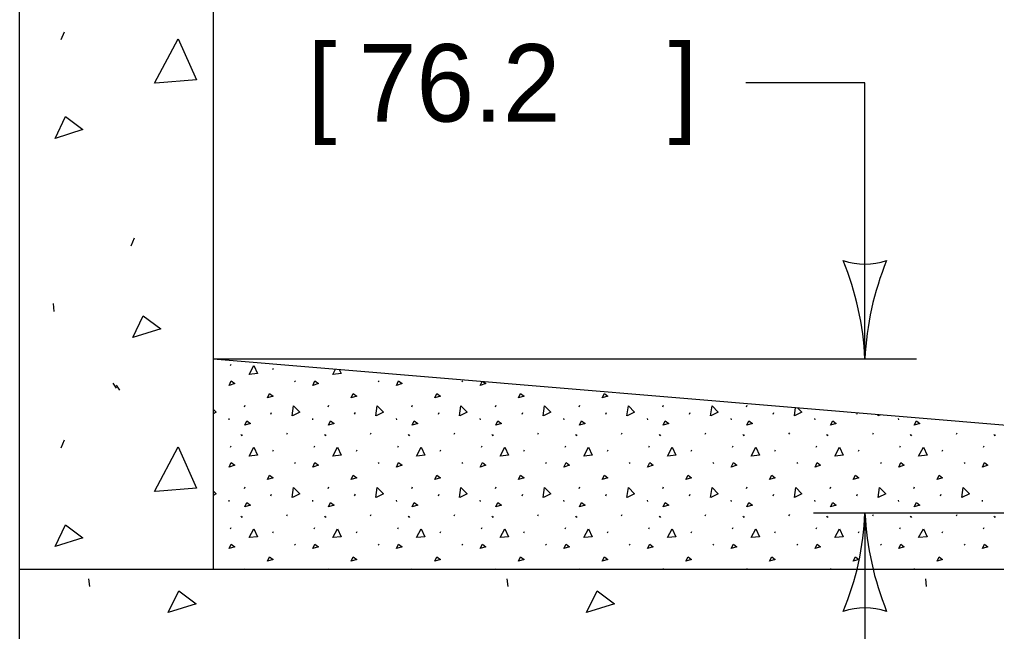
# Model space of a CAD drawing. Extents: x 49991.4 to 50041.6, y 49987.6 to 50011.4.
# Drawn here: x 50025.993 to 50026.75, y 49991.279 to 49991.752 of the extents above; entities that cross this region are included whole.
import ezdxf

# ---------------------------------------------------------------- set-up
doc = ezdxf.new("R2010")
doc.units = 0
for name, color, linetype in [('Level 1', 7, 'Continuous'), ('Level 2', 7, 'Continuous'), ('Level 3', 7, 'Continuous'), ('Level 4', 7, 'Continuous')]:
    doc.layers.add(name, color=color, linetype=linetype)

msp = doc.modelspace()

# ---------------------------------------------------------------- linework, layer by layer
at = {"layer": 'Level 1'}
for p, q in [((50025.99318, 49991.32695), (50025.99318, 49992.22695)), ((50026.0254, 49991.73689), (50026.02811, 49991.74298)), ((50026.07955, 49991.5772), (50026.08225, 49991.58329)), ((50026.01914, 49991.53246), (50026.01982, 49991.52637)), ((50026.14318, 49991.48968), (50027.58032, 49991.36954)), ((50026.06533, 49991.47097), (50026.06804, 49991.46691)), ((50026.06804, 49991.46942), (50026.07074, 49991.46536)), ((50026.0254, 49991.42081), (50026.02811, 49991.4269)), ((50026.04658, 49991.31948), (50026.04726, 49991.31339)), ((50026.37071, 49991.31948), (50026.37139, 49991.31339)), ((50026.69485, 49991.31948), (50026.69553, 49991.31339))]:
    msp.add_line(p, q, dxfattribs=at)
for points in [[(50025.99318, 49992.22695), (50026.14318, 49992.22695), (50026.14318, 49991.32695)], [(50026.09782, 49991.70306), (50026.11609, 49991.73757), (50026.1303, 49991.70577), (50026.09849, 49991.70306)], [(50026.02066, 49991.66043), (50026.02878, 49991.67735), (50026.04232, 49991.6672), (50026.02066, 49991.66043)], [(50026.0809, 49991.50615), (50026.08902, 49991.52307), (50026.10255, 49991.51292), (50026.0809, 49991.50615)], [(50026.09782, 49991.38698), (50026.11609, 49991.42148), (50026.1303, 49991.38968), (50026.09849, 49991.38698)], [(50026.02066, 49991.34434), (50026.02878, 49991.36126), (50026.04232, 49991.35111), (50026.02066, 49991.34434)], [(50025.99318, 49991.14695), (50025.99318, 49991.32695), (50027.72873, 49991.32695), (50027.72873, 49991.14695)], [(50026.10834, 49991.29317), (50026.11646, 49991.31009), (50026.12999, 49991.29994), (50026.10834, 49991.29317)], [(50026.43247, 49991.29317), (50026.44059, 49991.31009), (50026.45413, 49991.29994), (50026.43247, 49991.29317)]]:
    msp.add_lwpolyline(points, dxfattribs=at)
at = {"layer": 'Level 3'}
for p, q in [((50026.64808, 49991.70338), (50026.55581, 49991.70338)), ((50026.64808, 49991.48968), (50026.64808, 49991.70338)), ((50026.14318, 49991.48968), (50026.68808, 49991.48968)), ((50026.64808, 49991.37025), (50026.60808, 49991.37025)), ((50027.57184, 49991.37025), (50026.64808, 49991.37025)), ((50026.64808, 49991.37025), (50026.64808, 49991.09143))]:
    msp.add_line(p, q, dxfattribs=at)
for centre, radius, start, end in [((50026.64808, 49991.61789), 0.05477, 252.13882, 287.86118), ((50026.41536, 49991.47818), 0.233, 2.82731, 22.07716), ((50026.64808, 49991.61789), 0.05477, 252.13882, 287.86118), ((50026.41536, 49991.47818), 0.233, 2.82731, 22.07716), ((50026.87021, 49991.48052), 0.22232, 157.45601, 177.63952), ((50026.87021, 49991.48052), 0.22232, 157.45601, 177.63952), ((50026.42594, 49991.37941), 0.22232, 337.45601, 357.63952), ((50026.88079, 49991.38175), 0.233, 182.82731, 202.07716), ((50026.64808, 49991.24204), 0.05477, 72.13882, 107.86118)]:
    msp.add_arc(centre, radius, start, end, dxfattribs=at)
at = {"layer": 'Level 4'}
for p, q in [((50026.15653, 49991.48446), (50026.15707, 49991.48568)), ((50026.18929, 49991.48135), (50026.18983, 49991.48256)), ((50026.2062, 49991.47268), (50026.20674, 49991.47187)), ((50026.27103, 49991.47268), (50026.27157, 49991.47187)), ((50026.33586, 49991.47268), (50026.3364, 49991.47187)), ((50026.16736, 49991.45252), (50026.1679, 49991.45374)), ((50026.23219, 49991.45252), (50026.23273, 49991.45374)), ((50026.29702, 49991.45252), (50026.29756, 49991.45374)), ((50026.36184, 49991.45252), (50026.36239, 49991.45374)), ((50026.42667, 49991.45252), (50026.42721, 49991.45374)), ((50026.4915, 49991.45252), (50026.49204, 49991.45374)), ((50026.55633, 49991.45252), (50026.55687, 49991.45374)), ((50026.18793, 49991.44697), (50026.18847, 49991.44819)), ((50026.25276, 49991.44697), (50026.2533, 49991.44819)), ((50026.31759, 49991.44697), (50026.31813, 49991.44819)), ((50026.38242, 49991.44697), (50026.38296, 49991.44819)), ((50026.44724, 49991.44697), (50026.44778, 49991.44819)), ((50026.51207, 49991.44697), (50026.51261, 49991.44819)), ((50026.5769, 49991.44697), (50026.57744, 49991.44819)), ((50026.64173, 49991.44697), (50026.64217, 49991.44797)), ((50026.15528, 49991.44357), (50026.15542, 49991.44235)), ((50026.22011, 49991.44357), (50026.22024, 49991.44235)), ((50026.28494, 49991.44357), (50026.28507, 49991.44235)), ((50026.34976, 49991.44357), (50026.3499, 49991.44235)), ((50026.41459, 49991.44357), (50026.41473, 49991.44235)), ((50026.47942, 49991.44357), (50026.47955, 49991.44235)), ((50026.54425, 49991.44357), (50026.54438, 49991.44235)), ((50026.60907, 49991.44357), (50026.60921, 49991.44235)), ((50026.6739, 49991.44357), (50026.67404, 49991.44235)), ((50026.16452, 49991.43127), (50026.16506, 49991.43046)), ((50026.16506, 49991.43096), (50026.1656, 49991.43015)), ((50026.20025, 49991.43127), (50026.20079, 49991.43249)), ((50026.22935, 49991.43127), (50026.22989, 49991.43046)), ((50026.22989, 49991.43096), (50026.23043, 49991.43015)), ((50026.26508, 49991.43127), (50026.26562, 49991.43249)), ((50026.29417, 49991.43127), (50026.29471, 49991.43046)), ((50026.29471, 49991.43096), (50026.29526, 49991.43015)), ((50026.3299, 49991.43127), (50026.33044, 49991.43249)), ((50026.359, 49991.43127), (50026.35954, 49991.43046)), ((50026.35954, 49991.43096), (50026.36008, 49991.43015)), ((50026.39473, 49991.43127), (50026.39527, 49991.43249)), ((50026.42383, 49991.43127), (50026.42437, 49991.43046)), ((50026.42437, 49991.43096), (50026.42491, 49991.43015)), ((50026.45956, 49991.43127), (50026.4601, 49991.43249)), ((50026.48866, 49991.43127), (50026.4892, 49991.43046)), ((50026.4892, 49991.43096), (50026.48974, 49991.43015)), ((50026.52439, 49991.43127), (50026.52493, 49991.43249)), ((50026.55348, 49991.43127), (50026.55402, 49991.43046)), ((50026.55402, 49991.43096), (50026.55457, 49991.43015)), ((50026.58921, 49991.43127), (50026.58975, 49991.43249)), ((50026.61831, 49991.43127), (50026.61885, 49991.43046)), ((50026.61885, 49991.43096), (50026.61939, 49991.43015)), ((50026.65404, 49991.43127), (50026.65458, 49991.43249)), ((50026.68314, 49991.43127), (50026.68368, 49991.43046)), ((50026.68368, 49991.43096), (50026.68422, 49991.43015)), ((50026.71887, 49991.43127), (50026.71941, 49991.43249)), ((50026.74797, 49991.43127), (50026.74851, 49991.43046)), ((50026.74851, 49991.43096), (50026.74905, 49991.43015)), ((50026.15653, 49991.42124), (50026.15707, 49991.42246)), ((50026.22136, 49991.42124), (50026.2219, 49991.42246)), ((50026.28619, 49991.42124), (50026.28673, 49991.42246)), ((50026.35102, 49991.42124), (50026.35156, 49991.42246)), ((50026.41584, 49991.42124), (50026.41638, 49991.42246)), ((50026.48067, 49991.42124), (50026.48121, 49991.42246)), ((50026.5455, 49991.42124), (50026.54604, 49991.42246)), ((50026.61033, 49991.42124), (50026.61087, 49991.42246)), ((50026.67515, 49991.42124), (50026.67569, 49991.42246)), ((50026.73998, 49991.42124), (50026.74052, 49991.42246)), ((50026.18929, 49991.41813), (50026.18983, 49991.41935)), ((50026.25411, 49991.41813), (50026.25465, 49991.41935)), ((50026.31894, 49991.41813), (50026.31948, 49991.41935)), ((50026.38377, 49991.41813), (50026.38431, 49991.41935)), ((50026.4486, 49991.41813), (50026.44914, 49991.41935)), ((50026.51342, 49991.41813), (50026.51396, 49991.41935)), ((50026.57825, 49991.41813), (50026.57879, 49991.41935)), ((50026.64308, 49991.41813), (50026.64362, 49991.41935)), ((50026.70791, 49991.41813), (50026.70845, 49991.41935)), ((50026.2062, 49991.40947), (50026.20674, 49991.40865)), ((50026.27103, 49991.40947), (50026.27157, 49991.40865)), ((50026.33586, 49991.40947), (50026.3364, 49991.40865)), ((50026.40069, 49991.40947), (50026.40123, 49991.40865)), ((50026.46551, 49991.40947), (50026.46605, 49991.40865)), ((50026.53034, 49991.40947), (50026.53088, 49991.40865)), ((50026.59517, 49991.40947), (50026.59571, 49991.40865)), ((50026.66, 49991.40947), (50026.66054, 49991.40865)), ((50026.72482, 49991.40947), (50026.72536, 49991.40865)), ((50026.16736, 49991.3893), (50026.1679, 49991.39052)), ((50026.18793, 49991.38375), (50026.18847, 49991.38497)), ((50026.23219, 49991.3893), (50026.23273, 49991.39052)), ((50026.25276, 49991.38375), (50026.2533, 49991.38497)), ((50026.29702, 49991.3893), (50026.29756, 49991.39052)), ((50026.31759, 49991.38375), (50026.31813, 49991.38497)), ((50026.36184, 49991.3893), (50026.36239, 49991.39052)), ((50026.38242, 49991.38375), (50026.38296, 49991.38497)), ((50026.42667, 49991.3893), (50026.42721, 49991.39052)), ((50026.44724, 49991.38375), (50026.44778, 49991.38497)), ((50026.4915, 49991.3893), (50026.49204, 49991.39052)), ((50026.51207, 49991.38375), (50026.51261, 49991.38497)), ((50026.55633, 49991.3893), (50026.55687, 49991.39052)), ((50026.5769, 49991.38375), (50026.57744, 49991.38497)), ((50026.62115, 49991.3893), (50026.6217, 49991.39052)), ((50026.64173, 49991.38375), (50026.64227, 49991.38497)), ((50026.68598, 49991.3893), (50026.68652, 49991.39052)), ((50026.70655, 49991.38375), (50026.70709, 49991.38497)), ((50026.15528, 49991.38035), (50026.15542, 49991.37914)), ((50026.22011, 49991.38035), (50026.22024, 49991.37914)), ((50026.28494, 49991.38035), (50026.28507, 49991.37914)), ((50026.34976, 49991.38035), (50026.3499, 49991.37914)), ((50026.41459, 49991.38035), (50026.41473, 49991.37914)), ((50026.47942, 49991.38035), (50026.47955, 49991.37914)), ((50026.54425, 49991.38035), (50026.54438, 49991.37914)), ((50026.60907, 49991.38035), (50026.60921, 49991.37914)), ((50026.6739, 49991.38035), (50026.67404, 49991.37914)), ((50026.73873, 49991.38035), (50026.73886, 49991.37914)), ((50026.20025, 49991.36806), (50026.20079, 49991.36927)), ((50026.26508, 49991.36806), (50026.26562, 49991.36927)), ((50026.3299, 49991.36806), (50026.33044, 49991.36927)), ((50026.39473, 49991.36806), (50026.39527, 49991.36927)), ((50026.45956, 49991.36806), (50026.4601, 49991.36927)), ((50026.52439, 49991.36806), (50026.52493, 49991.36927)), ((50026.58921, 49991.36806), (50026.58975, 49991.36927)), ((50026.65404, 49991.36806), (50026.65458, 49991.36927)), ((50026.71887, 49991.36806), (50026.71941, 49991.36927)), ((50026.16452, 49991.36806), (50026.16506, 49991.36724)), ((50026.16506, 49991.36775), (50026.1656, 49991.36693)), ((50026.22935, 49991.36806), (50026.22989, 49991.36724)), ((50026.22989, 49991.36775), (50026.23043, 49991.36693)), ((50026.29417, 49991.36806), (50026.29471, 49991.36724)), ((50026.29471, 49991.36775), (50026.29526, 49991.36693)), ((50026.359, 49991.36806), (50026.35954, 49991.36724)), ((50026.35954, 49991.36775), (50026.36008, 49991.36693)), ((50026.42383, 49991.36806), (50026.42437, 49991.36724)), ((50026.42437, 49991.36775), (50026.42491, 49991.36693)), ((50026.48866, 49991.36806), (50026.4892, 49991.36724)), ((50026.4892, 49991.36775), (50026.48974, 49991.36693)), ((50026.55348, 49991.36806), (50026.55402, 49991.36724)), ((50026.55402, 49991.36775), (50026.55457, 49991.36693)), ((50026.61831, 49991.36806), (50026.61885, 49991.36724)), ((50026.61885, 49991.36775), (50026.61939, 49991.36693)), ((50026.68314, 49991.36806), (50026.68368, 49991.36724)), ((50026.68368, 49991.36775), (50026.68422, 49991.36693)), ((50026.74797, 49991.36806), (50026.74851, 49991.36724)), ((50026.74851, 49991.36775), (50026.74905, 49991.36693)), ((50026.15653, 49991.35802), (50026.15707, 49991.35924)), ((50026.18929, 49991.35491), (50026.18983, 49991.35613)), ((50026.22136, 49991.35802), (50026.2219, 49991.35924)), ((50026.25411, 49991.35491), (50026.25465, 49991.35613)), ((50026.28619, 49991.35802), (50026.28673, 49991.35924)), ((50026.31894, 49991.35491), (50026.31948, 49991.35613)), ((50026.35102, 49991.35802), (50026.35156, 49991.35924)), ((50026.38377, 49991.35491), (50026.38431, 49991.35613)), ((50026.41584, 49991.35802), (50026.41638, 49991.35924)), ((50026.4486, 49991.35491), (50026.44914, 49991.35613)), ((50026.48067, 49991.35802), (50026.48121, 49991.35924)), ((50026.51342, 49991.35491), (50026.51396, 49991.35613)), ((50026.5455, 49991.35802), (50026.54604, 49991.35924)), ((50026.57825, 49991.35491), (50026.57879, 49991.35613)), ((50026.61033, 49991.35802), (50026.61087, 49991.35924)), ((50026.64308, 49991.35491), (50026.64362, 49991.35613)), ((50026.67515, 49991.35802), (50026.67569, 49991.35924)), ((50026.70791, 49991.35491), (50026.70845, 49991.35613)), ((50026.73998, 49991.35802), (50026.74052, 49991.35924)), ((50026.2062, 49991.34625), (50026.20674, 49991.34544)), ((50026.27103, 49991.34625), (50026.27157, 49991.34544)), ((50026.33586, 49991.34625), (50026.3364, 49991.34544)), ((50026.40069, 49991.34625), (50026.40123, 49991.34544)), ((50026.46551, 49991.34625), (50026.46605, 49991.34544)), ((50026.53034, 49991.34625), (50026.53088, 49991.34544)), ((50026.59517, 49991.34625), (50026.59571, 49991.34544)), ((50026.66, 49991.34625), (50026.66054, 49991.34544)), ((50026.72482, 49991.34625), (50026.72536, 49991.34544)), ((50026.16774, 49991.32695), (50026.1679, 49991.3273)), ((50026.23257, 49991.32695), (50026.23273, 49991.3273)), ((50026.2974, 49991.32695), (50026.29756, 49991.3273)), ((50026.36223, 49991.32695), (50026.36239, 49991.3273)), ((50026.42705, 49991.32695), (50026.42721, 49991.3273)), ((50026.49188, 49991.32695), (50026.49204, 49991.3273)), ((50026.55671, 49991.32695), (50026.55687, 49991.3273)), ((50026.62154, 49991.32695), (50026.6217, 49991.3273)), ((50026.68636, 49991.32695), (50026.68652, 49991.3273))]:
    msp.add_line(p, q, dxfattribs=at)
for points in [[(50026.17102, 49991.47769), (50026.17467, 49991.48459), (50026.17751, 49991.47823), (50026.17115, 49991.47769)], [(50026.23584, 49991.47769), (50026.23799, 49991.48175)], [(50026.24088, 49991.48151), (50026.24234, 49991.47823), (50026.23598, 49991.47769)], [(50026.15559, 49991.46917), (50026.15721, 49991.47255), (50026.15992, 49991.47052), (50026.15559, 49991.46917)], [(50026.22041, 49991.46917), (50026.22204, 49991.47255), (50026.22474, 49991.47052), (50026.22041, 49991.46917)], [(50026.28524, 49991.46917), (50026.28686, 49991.47255), (50026.28957, 49991.47052), (50026.28524, 49991.46917)], [(50026.35007, 49991.46917), (50026.35155, 49991.47226)], [(50026.35214, 49991.47221), (50026.3544, 49991.47052), (50026.35007, 49991.46917)], [(50026.18525, 49991.45949), (50026.18688, 49991.46288), (50026.18958, 49991.46085), (50026.18525, 49991.45949)], [(50026.25008, 49991.45949), (50026.2517, 49991.46288), (50026.25441, 49991.46085), (50026.25008, 49991.45949)], [(50026.31491, 49991.45949), (50026.31653, 49991.46288), (50026.31924, 49991.46085), (50026.31491, 49991.45949)], [(50026.37974, 49991.45949), (50026.38136, 49991.46288), (50026.38407, 49991.46085), (50026.37974, 49991.45949)], [(50026.44456, 49991.45949), (50026.44619, 49991.46288), (50026.44889, 49991.46085), (50026.44456, 49991.45949)], [(50026.2044, 49991.44557), (50026.20547, 49991.45331), (50026.21032, 49991.4483), (50026.20452, 49991.44562)], [(50026.26922, 49991.44557), (50026.2703, 49991.45331), (50026.27514, 49991.4483), (50026.26935, 49991.44562)], [(50026.33405, 49991.44557), (50026.33512, 49991.45331), (50026.33997, 49991.4483), (50026.33418, 49991.44562)], [(50026.39888, 49991.44557), (50026.39995, 49991.45331), (50026.4048, 49991.4483), (50026.39901, 49991.44562)], [(50026.46371, 49991.44557), (50026.46478, 49991.45331), (50026.46963, 49991.4483), (50026.46383, 49991.44562)], [(50026.52853, 49991.44557), (50026.52961, 49991.45331), (50026.53445, 49991.4483), (50026.52866, 49991.44562)], [(50026.14318, 49991.45069), (50026.14549, 49991.4483), (50026.14318, 49991.44723)], [(50026.59336, 49991.44557), (50026.59425, 49991.45197)], [(50026.59586, 49991.45184), (50026.59928, 49991.4483), (50026.59349, 49991.44562)], [(50026.65819, 49991.44557), (50026.65833, 49991.44661)], [(50026.66014, 49991.44646), (50026.65832, 49991.44562)], [(50026.16763, 49991.43831), (50026.16926, 49991.44169), (50026.17196, 49991.43966), (50026.16763, 49991.43831)], [(50026.23246, 49991.43831), (50026.23408, 49991.44169), (50026.23679, 49991.43966), (50026.23246, 49991.43831)], [(50026.29729, 49991.43831), (50026.29891, 49991.44169), (50026.30162, 49991.43966), (50026.29729, 49991.43831)], [(50026.36212, 49991.43831), (50026.36374, 49991.44169), (50026.36645, 49991.43966), (50026.36212, 49991.43831)], [(50026.42694, 49991.43831), (50026.42857, 49991.44169), (50026.43127, 49991.43966), (50026.42694, 49991.43831)], [(50026.49177, 49991.43831), (50026.49339, 49991.44169), (50026.4961, 49991.43966), (50026.49177, 49991.43831)], [(50026.5566, 49991.43831), (50026.55822, 49991.44169), (50026.56093, 49991.43966), (50026.5566, 49991.43831)], [(50026.62143, 49991.43831), (50026.62305, 49991.44169), (50026.62576, 49991.43966), (50026.62143, 49991.43831)], [(50026.68625, 49991.43831), (50026.68788, 49991.44169), (50026.69058, 49991.43966), (50026.68625, 49991.43831)], [(50026.17102, 49991.41447), (50026.17467, 49991.42138), (50026.17751, 49991.41502), (50026.17115, 49991.41447)], [(50026.23584, 49991.41447), (50026.2395, 49991.42138), (50026.24234, 49991.41502), (50026.23598, 49991.41447)], [(50026.30067, 49991.41447), (50026.30432, 49991.42138), (50026.30717, 49991.41502), (50026.30081, 49991.41447)], [(50026.3655, 49991.41447), (50026.36915, 49991.42138), (50026.37199, 49991.41502), (50026.36563, 49991.41447)], [(50026.43033, 49991.41447), (50026.43398, 49991.42138), (50026.43682, 49991.41502), (50026.43046, 49991.41447)], [(50026.49515, 49991.41447), (50026.49881, 49991.42138), (50026.50165, 49991.41502), (50026.49529, 49991.41447)], [(50026.55998, 49991.41447), (50026.56363, 49991.42138), (50026.56648, 49991.41502), (50026.56012, 49991.41447)], [(50026.62481, 49991.41447), (50026.62846, 49991.42138), (50026.6313, 49991.41502), (50026.62494, 49991.41447)], [(50026.68964, 49991.41447), (50026.69329, 49991.42138), (50026.69613, 49991.41502), (50026.68977, 49991.41447)], [(50026.15559, 49991.40595), (50026.15721, 49991.40933), (50026.15992, 49991.4073), (50026.15559, 49991.40595)], [(50026.22041, 49991.40595), (50026.22204, 49991.40933), (50026.22474, 49991.4073), (50026.22041, 49991.40595)], [(50026.28524, 49991.40595), (50026.28686, 49991.40933), (50026.28957, 49991.4073), (50026.28524, 49991.40595)], [(50026.35007, 49991.40595), (50026.35169, 49991.40933), (50026.3544, 49991.4073), (50026.35007, 49991.40595)], [(50026.4149, 49991.40595), (50026.41652, 49991.40933), (50026.41923, 49991.4073), (50026.4149, 49991.40595)], [(50026.47972, 49991.40595), (50026.48135, 49991.40933), (50026.48405, 49991.4073), (50026.47972, 49991.40595)], [(50026.54455, 49991.40595), (50026.54617, 49991.40933), (50026.54888, 49991.4073), (50026.54455, 49991.40595)], [(50026.60938, 49991.40595), (50026.611, 49991.40933), (50026.61371, 49991.4073), (50026.60938, 49991.40595)], [(50026.67421, 49991.40595), (50026.67583, 49991.40933), (50026.67854, 49991.4073), (50026.67421, 49991.40595)], [(50026.73903, 49991.40595), (50026.74066, 49991.40933), (50026.74336, 49991.4073), (50026.73903, 49991.40595)], [(50026.18525, 49991.39627), (50026.18688, 49991.39966), (50026.18958, 49991.39763), (50026.18525, 49991.39627)], [(50026.25008, 49991.39627), (50026.2517, 49991.39966), (50026.25441, 49991.39763), (50026.25008, 49991.39627)], [(50026.31491, 49991.39627), (50026.31653, 49991.39966), (50026.31924, 49991.39763), (50026.31491, 49991.39627)], [(50026.37974, 49991.39627), (50026.38136, 49991.39966), (50026.38407, 49991.39763), (50026.37974, 49991.39627)], [(50026.44456, 49991.39627), (50026.44619, 49991.39966), (50026.44889, 49991.39763), (50026.44456, 49991.39627)], [(50026.50939, 49991.39627), (50026.51101, 49991.39966), (50026.51372, 49991.39763), (50026.50939, 49991.39627)], [(50026.57422, 49991.39627), (50026.57584, 49991.39966), (50026.57855, 49991.39763), (50026.57422, 49991.39627)], [(50026.63905, 49991.39627), (50026.64067, 49991.39966), (50026.64338, 49991.39763), (50026.63905, 49991.39627)], [(50026.70387, 49991.39627), (50026.7055, 49991.39966), (50026.7082, 49991.39763), (50026.70387, 49991.39627)], [(50026.14318, 49991.38747), (50026.14549, 49991.38508), (50026.14318, 49991.38401)], [(50026.2044, 49991.38235), (50026.20547, 49991.39009), (50026.21032, 49991.38508), (50026.20452, 49991.3824)], [(50026.26922, 49991.38235), (50026.2703, 49991.39009), (50026.27514, 49991.38508), (50026.26935, 49991.3824)], [(50026.33405, 49991.38235), (50026.33512, 49991.39009), (50026.33997, 49991.38508), (50026.33418, 49991.3824)], [(50026.39888, 49991.38235), (50026.39995, 49991.39009), (50026.4048, 49991.38508), (50026.39901, 49991.3824)], [(50026.46371, 49991.38235), (50026.46478, 49991.39009), (50026.46963, 49991.38508), (50026.46383, 49991.3824)], [(50026.52853, 49991.38235), (50026.52961, 49991.39009), (50026.53445, 49991.38508), (50026.52866, 49991.3824)], [(50026.59336, 49991.38235), (50026.59443, 49991.39009), (50026.59928, 49991.38508), (50026.59349, 49991.3824)], [(50026.65819, 49991.38235), (50026.65926, 49991.39009), (50026.66411, 49991.38508), (50026.65832, 49991.3824)], [(50026.72302, 49991.38235), (50026.72409, 49991.39009), (50026.72894, 49991.38508), (50026.72314, 49991.3824)], [(50026.16763, 49991.37509), (50026.16926, 49991.37848), (50026.17196, 49991.37645), (50026.16763, 49991.37509)], [(50026.23246, 49991.37509), (50026.23408, 49991.37848), (50026.23679, 49991.37645), (50026.23246, 49991.37509)], [(50026.29729, 49991.37509), (50026.29891, 49991.37848), (50026.30162, 49991.37645), (50026.29729, 49991.37509)], [(50026.36212, 49991.37509), (50026.36374, 49991.37848), (50026.36645, 49991.37645), (50026.36212, 49991.37509)], [(50026.42694, 49991.37509), (50026.42857, 49991.37848), (50026.43127, 49991.37645), (50026.42694, 49991.37509)], [(50026.49177, 49991.37509), (50026.49339, 49991.37848), (50026.4961, 49991.37645), (50026.49177, 49991.37509)], [(50026.5566, 49991.37509), (50026.55822, 49991.37848), (50026.56093, 49991.37645), (50026.5566, 49991.37509)], [(50026.62143, 49991.37509), (50026.62305, 49991.37848), (50026.62576, 49991.37645), (50026.62143, 49991.37509)], [(50026.68625, 49991.37509), (50026.68788, 49991.37848), (50026.69058, 49991.37645), (50026.68625, 49991.37509)], [(50026.17102, 49991.35126), (50026.17467, 49991.35816), (50026.17751, 49991.3518), (50026.17115, 49991.35126)], [(50026.23584, 49991.35126), (50026.2395, 49991.35816), (50026.24234, 49991.3518), (50026.23598, 49991.35126)], [(50026.30067, 49991.35126), (50026.30432, 49991.35816), (50026.30717, 49991.3518), (50026.30081, 49991.35126)], [(50026.3655, 49991.35126), (50026.36915, 49991.35816), (50026.37199, 49991.3518), (50026.36563, 49991.35126)], [(50026.43033, 49991.35126), (50026.43398, 49991.35816), (50026.43682, 49991.3518), (50026.43046, 49991.35126)], [(50026.49515, 49991.35126), (50026.49881, 49991.35816), (50026.50165, 49991.3518), (50026.49529, 49991.35126)], [(50026.55998, 49991.35126), (50026.56363, 49991.35816), (50026.56648, 49991.3518), (50026.56012, 49991.35126)], [(50026.62481, 49991.35126), (50026.62846, 49991.35816), (50026.6313, 49991.3518), (50026.62494, 49991.35126)], [(50026.68964, 49991.35126), (50026.69329, 49991.35816), (50026.69613, 49991.3518), (50026.68977, 49991.35126)], [(50026.15559, 49991.34273), (50026.15721, 49991.34611), (50026.15992, 49991.34408), (50026.15559, 49991.34273)], [(50026.22041, 49991.34273), (50026.22204, 49991.34611), (50026.22474, 49991.34408), (50026.22041, 49991.34273)], [(50026.28524, 49991.34273), (50026.28686, 49991.34611), (50026.28957, 49991.34408), (50026.28524, 49991.34273)], [(50026.35007, 49991.34273), (50026.35169, 49991.34611), (50026.3544, 49991.34408), (50026.35007, 49991.34273)], [(50026.4149, 49991.34273), (50026.41652, 49991.34611), (50026.41923, 49991.34408), (50026.4149, 49991.34273)], [(50026.47972, 49991.34273), (50026.48135, 49991.34611), (50026.48405, 49991.34408), (50026.47972, 49991.34273)], [(50026.54455, 49991.34273), (50026.54617, 49991.34611), (50026.54888, 49991.34408), (50026.54455, 49991.34273)], [(50026.60938, 49991.34273), (50026.611, 49991.34611), (50026.61371, 49991.34408), (50026.60938, 49991.34273)], [(50026.67421, 49991.34273), (50026.67583, 49991.34611), (50026.67854, 49991.34408), (50026.67421, 49991.34273)], [(50026.73903, 49991.34273), (50026.74066, 49991.34611), (50026.74336, 49991.34408), (50026.73903, 49991.34273)], [(50026.18525, 49991.33306), (50026.18688, 49991.33644), (50026.18958, 49991.33441), (50026.18525, 49991.33306)], [(50026.25008, 49991.33306), (50026.2517, 49991.33644), (50026.25441, 49991.33441), (50026.25008, 49991.33306)], [(50026.31491, 49991.33306), (50026.31653, 49991.33644), (50026.31924, 49991.33441), (50026.31491, 49991.33306)], [(50026.37974, 49991.33306), (50026.38136, 49991.33644), (50026.38407, 49991.33441), (50026.37974, 49991.33306)], [(50026.44456, 49991.33306), (50026.44619, 49991.33644), (50026.44889, 49991.33441), (50026.44456, 49991.33306)], [(50026.50939, 49991.33306), (50026.51101, 49991.33644), (50026.51372, 49991.33441), (50026.50939, 49991.33306)], [(50026.57422, 49991.33306), (50026.57584, 49991.33644), (50026.57855, 49991.33441), (50026.57422, 49991.33306)], [(50026.63905, 49991.33306), (50026.64067, 49991.33644), (50026.64338, 49991.33441), (50026.63905, 49991.33306)], [(50026.70387, 49991.33306), (50026.7055, 49991.33644), (50026.7082, 49991.33441), (50026.70387, 49991.33306)]]:
    msp.add_lwpolyline(points, dxfattribs=at)

# ---------------------------------------------------------------- texts
at = {"layer": 'Level 2'}
for s, p in [('[', (50026.21628, 49991.67338)), ('76.2', (50026.25597, 49991.67338)), (']', (50026.49597, 49991.67338))]:
    msp.add_text(s, height=0.06, rotation=360, dxfattribs=at).set_placement(p)

doc.saveas('drawing.dxf')
